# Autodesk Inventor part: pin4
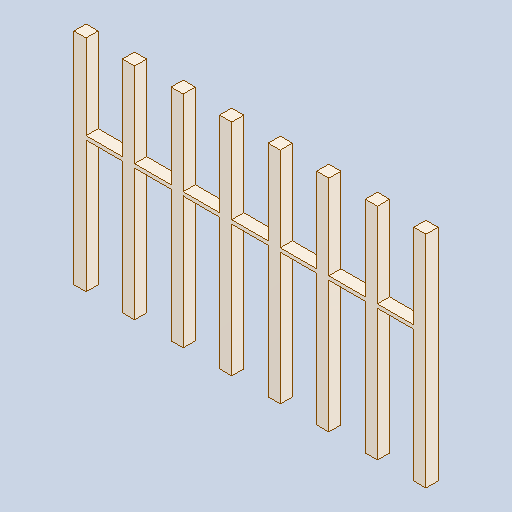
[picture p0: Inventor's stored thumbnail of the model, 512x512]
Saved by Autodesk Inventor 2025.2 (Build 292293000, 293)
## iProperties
Created: 2025-04
Part Number: pin4
Material: Generic
Description: PART--DESC
Document SubType Name: Modeling
Designer: BennF
Density: 1 g/cm^3
Appearance: Default
Author: BennF
Revision Number: NONE
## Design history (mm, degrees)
feature "Solid"
body "Solid1"
